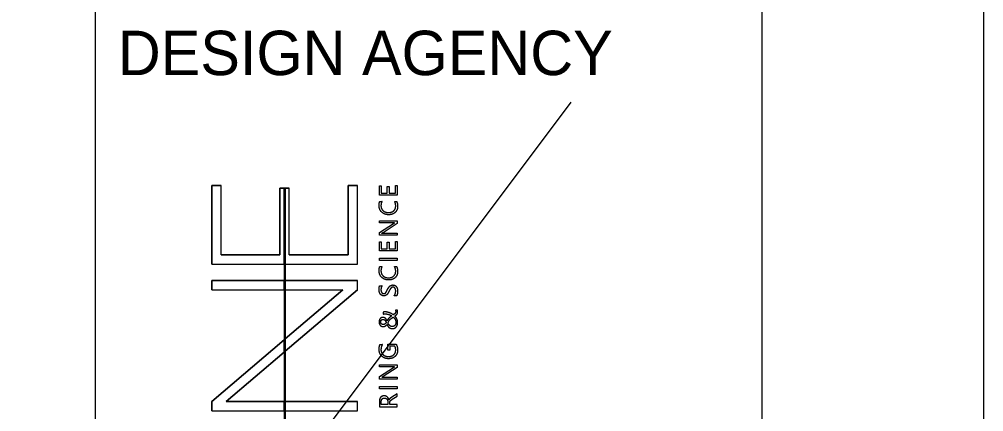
# Model space of a CAD drawing. Extents: x 0 to 34, y -1.8 to 22.
# Drawn here: x 31.828 to 34, y 3.592 to 4.476 of the extents above; entities that cross this region are included whole.
import ezdxf

# ---------------------------------------------------------------- set-up
doc = ezdxf.new("R2010")
doc.units = 0
for name, color, linetype in [('CS-ALGN-TEXT', 7, 'Continuous'), ('CS-ANNO', 7, 'Continuous'), ('CS-ANNO-MATC', 7, 'Continuous'), ('CS-PROF-TEXT', 7, 'Continuous')]:
    doc.layers.add(name, color=color, linetype=linetype)

msp = doc.modelspace()

# ---------------------------------------------------------------- linework, layer by layer
at = {"layer": 'CS-ALGN-TEXT'}
msp.add_lwpolyline([(0, 0), (34, 0), (34, 22), (0, 22)], close=True, dxfattribs=at)
at = {"layer": 'CS-ANNO'}
msp.add_line((32, 0.5), (32, 21.5), dxfattribs=at)
msp.add_lwpolyline([(1.5, 21.5), (33.5, 21.5), (33.5, 0.5), (1.5, 0.5)], close=True, dxfattribs=at)
at = {"layer": 'CS-ANNO-MATC'}
for p, q in [((32.2617, 4.1013), (32.2828, 4.1013)), ((32.2617, 3.9242), (32.2617, 4.1013)), ((32.2828, 3.9453), (32.2828, 4.1013)), ((32.4151, 3.9453), (32.4151, 4.0956)), ((32.4151, 4.0956), (32.4244, 4.0956)), ((32.4244, 4.0956), (32.4244, 3.4676)), ((32.4244, 4.0956), (32.4244, 3.9242)), ((32.4244, 4.0956), (32.4269, 4.0956)), ((32.4269, 4.0956), (32.4269, 3.4676)), ((32.4269, 4.0956), (32.4269, 3.9242)), ((32.4269, 4.0956), (32.4362, 4.0956)), ((32.4362, 3.9453), (32.4362, 4.0956)), ((32.5685, 4.1013), (32.5896, 4.1013)), ((32.5685, 3.9453), (32.5685, 4.1013)), ((32.5896, 3.9242), (32.5896, 4.1013)), ((32.64, 4.0658), (32.645, 4.0658)), ((32.6731, 4.0658), (32.6777, 4.0658)), ((32.6734, 4.0173), (32.6734, 4.0174)), ((32.6446, 3.994), (32.6446, 3.9938)), ((32.2828, 3.9453), (32.4151, 3.9453)), ((32.4362, 3.9453), (32.5685, 3.9453)), ((32.2617, 3.9242), (32.4244, 3.9242)), ((32.4269, 3.9242), (32.5896, 3.9242)), ((32.64, 3.919), (32.645, 3.919)), ((32.6731, 3.919), (32.6777, 3.919)), ((32.2617, 3.8665), (32.2617, 3.8876)), ((32.2617, 3.8876), (32.4244, 3.8876)), ((32.2617, 3.8665), (32.4244, 3.8665)), ((32.4244, 3.8876), (32.4244, 3.8665)), ((32.4269, 3.8876), (32.4269, 3.8665)), ((32.4269, 3.8876), (32.5896, 3.8876)), ((32.4269, 3.7561), (32.5568, 3.8665)), ((32.5896, 3.8665), (32.4269, 3.7283)), ((32.4269, 3.8665), (32.5568, 3.8665)), ((32.5896, 3.8665), (32.5896, 3.8876)), ((32.6397, 3.8758), (32.6451, 3.8758)), ((32.6778, 3.853), (32.6722, 3.853)), ((32.6478, 3.8165), (32.6478, 3.812)), ((32.6793, 3.821), (32.675, 3.821)), ((32.6801, 3.8167), (32.6801, 3.8167)), ((32.6473, 3.8001), (32.6473, 3.8001)), ((32.6761, 3.793), (32.6761, 3.793)), ((32.2617, 3.6155), (32.4244, 3.7539)), ((32.4244, 3.7539), (32.4244, 3.7261)), ((32.4269, 3.7561), (32.4269, 3.7283)), ((32.6404, 3.7435), (32.6457, 3.7435)), ((32.4244, 3.7261), (32.2943, 3.6155)), ((32.6734, 3.6931), (32.6734, 3.6932)), ((32.6446, 3.6698), (32.6446, 3.6696)), ((32.2617, 3.5944), (32.2617, 3.6155)), ((32.2943, 3.6155), (32.4244, 3.6155)), ((32.4244, 3.6155), (32.4244, 3.5944)), ((32.4269, 3.6155), (32.4269, 3.5944)), ((32.4269, 3.6155), (32.5896, 3.6155)), ((32.5896, 3.5944), (32.5896, 3.6155)), ((32.6607, 3.6189), (32.6606, 3.6189)), ((32.2617, 3.5944), (32.4244, 3.5944)), ((32.4269, 3.5944), (32.5896, 3.5944))]:
    msp.add_line(p, q, dxfattribs=at)
for points in [[(32.2617, 4.1013), (32.2617, 3.9242), (32.4244, 3.9242), (32.4244, 4.0956), (32.4151, 4.0956), (32.4151, 3.9453), (32.2828, 3.9453), (32.2828, 4.1013)], [(32.4362, 3.9453), (32.4362, 4.0956), (32.4269, 4.0956), (32.4269, 3.9242), (32.5896, 3.9242), (32.5896, 4.1013), (32.5685, 4.1013), (32.5685, 3.9453)], [(32.6794, 4.1013), (32.6794, 4.0799), (32.639, 4.0799), (32.639, 4.1004), (32.6433, 4.1004), (32.6433, 4.0846), (32.6567, 4.0846), (32.6567, 4.0992), (32.661, 4.0992), (32.661, 4.0846), (32.6751, 4.0846), (32.6751, 4.1013)], [(32.6794, 3.9757), (32.6794, 3.9542), (32.639, 3.9542), (32.639, 3.9747), (32.6433, 3.9747), (32.6433, 3.959), (32.6567, 3.959), (32.6567, 3.9736), (32.661, 3.9736), (32.661, 3.959), (32.6751, 3.959), (32.6751, 3.9757)], [(32.6794, 3.9377), (32.6794, 3.933), (32.639, 3.933), (32.639, 3.9377)], [(32.2617, 3.8876), (32.2617, 3.8665), (32.4244, 3.8665), (32.4244, 3.8876)], [(32.4269, 3.8876), (32.4269, 3.8665), (32.5568, 3.8665), (32.4269, 3.7561), (32.4269, 3.7283), (32.5896, 3.8665), (32.5896, 3.8876)], [(32.2617, 3.6155), (32.2617, 3.5944), (32.4244, 3.5944), (32.4244, 3.6155), (32.2943, 3.6155), (32.4244, 3.7261), (32.4244, 3.7539)], [(32.6794, 3.6486), (32.6794, 3.6439), (32.639, 3.6439), (32.639, 3.6486)], [(32.4269, 3.6155), (32.4269, 3.5944), (32.5896, 3.5944), (32.5896, 3.6155)]]:
    msp.add_lwpolyline(points, close=True, dxfattribs=at)
for points in [[(32.5359, 3.464), (32.4295, 3.4377), (32.4295, 3.4676), (32.4269, 3.4676), (32.4269, 4.0956), (32.4244, 4.0956), (32.4244, 3.4676), (32.4219, 3.4676), (32.4219, 3.4358), (32.3625, 3.4211)], [(32.6675, 4.0171), (32.639, 4.0171), (32.639, 4.0219), (32.6794, 4.0219), (32.6794, 4.0161), (32.6472, 3.9953)], [(32.6502, 3.994), (32.6794, 3.994), (32.6794, 3.9893), (32.639, 3.9893), (32.639, 3.9954), (32.6707, 4.0157)], [(32.6739, 3.7396), (32.6626, 3.7396), (32.6626, 3.7308), (32.6583, 3.7308), (32.6583, 3.7444), (32.6766, 3.7444)], [(32.6675, 3.6929), (32.639, 3.6929), (32.639, 3.6977), (32.6794, 3.6977), (32.6794, 3.6919), (32.6472, 3.6711)], [(32.6502, 3.6698), (32.6794, 3.6698), (32.6794, 3.6651), (32.639, 3.6651), (32.639, 3.6712), (32.6707, 3.6915)], [(32.6681, 3.6201), (32.6794, 3.6268), (32.6794, 3.6325), (32.6673, 3.6249)], [(32.639, 3.6156), (32.639, 3.6035), (32.6794, 3.6035), (32.6794, 3.6082), (32.6622, 3.6082), (32.6622, 3.6121)], [(32.6579, 3.6147), (32.6579, 3.6082), (32.6433, 3.6082), (32.6433, 3.6147)]]:
    msp.add_lwpolyline(points, dxfattribs=at)
for points in [[(32.6383, 4.0563), (32.6383, 4.062), (32.64, 4.0658)], [(32.645, 4.0658), (32.6426, 4.0615), (32.6426, 4.0562)], [(32.6758, 4.0553), (32.6758, 4.0614), (32.6731, 4.0658)], [(32.6777, 4.0658), (32.6801, 4.0613), (32.6801, 4.0547)], [(32.6443, 4.0415), (32.6383, 4.0473), (32.6383, 4.0563)], [(32.6426, 4.0562), (32.6426, 4.0493), (32.6472, 4.0449)], [(32.66, 4.0357), (32.6503, 4.0357), (32.6443, 4.0415)], [(32.6472, 4.0449), (32.6519, 4.0406), (32.6597, 4.0406)], [(32.6597, 4.0406), (32.6671, 4.0406), (32.6714, 4.0447)], [(32.6745, 4.0408), (32.669, 4.0357), (32.66, 4.0357)], [(32.6714, 4.0447), (32.6758, 4.0487), (32.6758, 4.0553)], [(32.6801, 4.0547), (32.6801, 4.046), (32.6745, 4.0408)], [(32.6734, 4.0174), (32.6717, 4.0171), (32.6675, 4.0171)], [(32.6707, 4.0157), (32.6727, 4.0169), (32.6734, 4.0173)], [(32.6472, 3.9953), (32.646, 3.9945), (32.6446, 3.994)], [(32.6446, 3.9938), (32.6459, 3.994), (32.6502, 3.994)], [(32.6383, 3.9094), (32.6383, 3.9152), (32.64, 3.919)], [(32.645, 3.919), (32.6426, 3.9146), (32.6426, 3.9094)], [(32.6758, 3.9084), (32.6758, 3.9145), (32.6731, 3.919)], [(32.6777, 3.919), (32.6801, 3.9145), (32.6801, 3.9078)], [(32.6443, 3.8946), (32.6383, 3.9005), (32.6383, 3.9094)], [(32.6426, 3.9094), (32.6426, 3.9024), (32.6472, 3.8981)], [(32.66, 3.8888), (32.6503, 3.8888), (32.6443, 3.8946)], [(32.6472, 3.8981), (32.6519, 3.8937), (32.6597, 3.8937)], [(32.6597, 3.8937), (32.6671, 3.8937), (32.6714, 3.8978)], [(32.6745, 3.894), (32.669, 3.8888), (32.66, 3.8888)], [(32.6714, 3.8978), (32.6758, 3.9018), (32.6758, 3.9084)], [(32.6801, 3.9078), (32.6801, 3.8992), (32.6745, 3.894)], [(32.6383, 3.8671), (32.6383, 3.8731), (32.6397, 3.8758)], [(32.6389, 3.862), (32.6383, 3.8645), (32.6383, 3.8671)], [(32.6451, 3.8758), (32.6426, 3.8723), (32.6426, 3.8667)], [(32.6426, 3.8667), (32.6426, 3.8651), (32.6429, 3.8636)], [(32.6552, 3.8631), (32.6561, 3.8647), (32.6571, 3.8668)], [(32.6571, 3.8668), (32.6582, 3.869), (32.6594, 3.8709)], [(32.6594, 3.8709), (32.6606, 3.8729), (32.662, 3.8744)], [(32.6626, 3.8669), (32.6616, 3.8651), (32.6606, 3.8631)], [(32.662, 3.8744), (32.6634, 3.8758), (32.6652, 3.8767)], [(32.6645, 3.8699), (32.6635, 3.8686), (32.6626, 3.8669)], [(32.6667, 3.8719), (32.6655, 3.8711), (32.6645, 3.8699)], [(32.6652, 3.8767), (32.6669, 3.8775), (32.6692, 3.8775)], [(32.6695, 3.8726), (32.6679, 3.8726), (32.6667, 3.8719)], [(32.6692, 3.8775), (32.6722, 3.8775), (32.6743, 3.8764)], [(32.6742, 3.8704), (32.6726, 3.8726), (32.6695, 3.8726)], [(32.6758, 3.8639), (32.6758, 3.8683), (32.6742, 3.8704)], [(32.6743, 3.8764), (32.6763, 3.8752), (32.6776, 3.8732)], [(32.6776, 3.8732), (32.6789, 3.8712), (32.6795, 3.8686)], [(32.6795, 3.8686), (32.6801, 3.866), (32.6801, 3.8632)], [(32.6409, 3.8575), (32.6396, 3.8595), (32.6389, 3.862)], [(32.6443, 3.8543), (32.6422, 3.8555), (32.6409, 3.8575)], [(32.6429, 3.8636), (32.6432, 3.862), (32.644, 3.8608)], [(32.644, 3.8608), (32.6447, 3.8596), (32.6459, 3.8588)], [(32.6491, 3.8531), (32.6463, 3.8531), (32.6443, 3.8543)], [(32.6459, 3.8588), (32.647, 3.8581), (32.6487, 3.8581)], [(32.6487, 3.8581), (32.6502, 3.8581), (32.6514, 3.8586)], [(32.653, 3.8539), (32.6514, 3.8531), (32.6491, 3.8531)], [(32.6514, 3.8586), (32.6525, 3.8592), (32.6534, 3.8603)], [(32.656, 3.856), (32.6547, 3.8546), (32.653, 3.8539)], [(32.6534, 3.8603), (32.6543, 3.8615), (32.6552, 3.8631)], [(32.6585, 3.8592), (32.6574, 3.8573), (32.656, 3.856)], [(32.6606, 3.8631), (32.6596, 3.861), (32.6585, 3.8592)], [(32.6722, 3.853), (32.673, 3.854), (32.6737, 3.8553)], [(32.6737, 3.8553), (32.6744, 3.8567), (32.6749, 3.8582)], [(32.6749, 3.8582), (32.6753, 3.8596), (32.6756, 3.8611)], [(32.6756, 3.8611), (32.6758, 3.8626), (32.6758, 3.8639)], [(32.6787, 3.8551), (32.6783, 3.8538), (32.6778, 3.853)], [(32.6795, 3.8579), (32.6792, 3.8564), (32.6787, 3.8551)], [(32.6799, 3.8608), (32.6798, 3.8594), (32.6795, 3.8579)], [(32.6801, 3.8632), (32.6801, 3.8622), (32.6799, 3.8608)], [(32.6406, 3.8016), (32.6395, 3.8003), (32.6389, 3.7985)], [(32.6433, 3.8037), (32.6418, 3.8029), (32.6406, 3.8016)], [(32.6469, 3.8044), (32.6449, 3.8044), (32.6433, 3.8037)], [(32.6525, 3.8025), (32.6503, 3.8044), (32.6469, 3.8044)], [(32.6496, 3.8168), (32.6487, 3.8167), (32.6478, 3.8165)], [(32.6478, 3.812), (32.6487, 3.8122), (32.6497, 3.8124)], [(32.6516, 3.8169), (32.6504, 3.8168), (32.6496, 3.8168)], [(32.6497, 3.8124), (32.6506, 3.8125), (32.6517, 3.8125)], [(32.6567, 3.8163), (32.6541, 3.8169), (32.6516, 3.8169)], [(32.6517, 3.8125), (32.6559, 3.8125), (32.6597, 3.8113)], [(32.6563, 3.7967), (32.6547, 3.8005), (32.6525, 3.8025)], [(32.6617, 3.8149), (32.6593, 3.8158), (32.6567, 3.8163)], [(32.6606, 3.8031), (32.6593, 3.8018), (32.6582, 3.8002)], [(32.6597, 3.8113), (32.6636, 3.8102), (32.6667, 3.8079)], [(32.6635, 3.8056), (32.662, 3.8045), (32.6606, 3.8031)], [(32.6664, 3.8128), (32.6642, 3.814), (32.6617, 3.8149)], [(32.6625, 3.7992), (32.6639, 3.8007), (32.6658, 3.8021)], [(32.6667, 3.8079), (32.6651, 3.8068), (32.6635, 3.8056)], [(32.6658, 3.8021), (32.6677, 3.8036), (32.6704, 3.8053)], [(32.6704, 3.8103), (32.6686, 3.8116), (32.6664, 3.8128)], [(32.6728, 3.8121), (32.6718, 3.8113), (32.6704, 3.8103)], [(32.6704, 3.8053), (32.6715, 3.8043), (32.6725, 3.803)], [(32.6725, 3.803), (32.6736, 3.8018), (32.6743, 3.8003)], [(32.6744, 3.8137), (32.6738, 3.8129), (32.6728, 3.8121)], [(32.6738, 3.8075), (32.6753, 3.8086), (32.6764, 3.8095)], [(32.6761, 3.8049), (32.675, 3.8064), (32.6738, 3.8075)], [(32.6754, 3.8154), (32.6751, 3.8146), (32.6744, 3.8137)], [(32.675, 3.821), (32.6753, 3.8201), (32.6755, 3.8192)], [(32.6758, 3.8175), (32.6758, 3.8163), (32.6754, 3.8154)], [(32.6755, 3.8192), (32.6758, 3.8183), (32.6758, 3.8175)], [(32.6781, 3.8016), (32.6773, 3.8034), (32.6761, 3.8049)], [(32.6764, 3.8095), (32.6776, 3.8105), (32.6784, 3.8116)], [(32.6795, 3.7977), (32.679, 3.7998), (32.6781, 3.8016)], [(32.6784, 3.8116), (32.6792, 3.8126), (32.6796, 3.8138)], [(32.6799, 3.8189), (32.6797, 3.82), (32.6793, 3.821)], [(32.6796, 3.8138), (32.6801, 3.8151), (32.6801, 3.8167)], [(32.6801, 3.8167), (32.6801, 3.8177), (32.6799, 3.8189)], [(32.6389, 3.7985), (32.6383, 3.7967), (32.6383, 3.7945)], [(32.6383, 3.7945), (32.6383, 3.7923), (32.6389, 3.7903)], [(32.6389, 3.7903), (32.6395, 3.7884), (32.6407, 3.787)], [(32.6407, 3.787), (32.6419, 3.7856), (32.6436, 3.7848)], [(32.642, 3.7945), (32.642, 3.7954), (32.6423, 3.7964)], [(32.6435, 3.7901), (32.642, 3.7917), (32.642, 3.7945)], [(32.6423, 3.7964), (32.6426, 3.7974), (32.6432, 3.7982)], [(32.6432, 3.7982), (32.6439, 3.799), (32.6449, 3.7995)], [(32.6475, 3.7884), (32.645, 3.7884), (32.6435, 3.7901)], [(32.6436, 3.7848), (32.6453, 3.784), (32.6475, 3.784)], [(32.6449, 3.7995), (32.6459, 3.8001), (32.6473, 3.8001)], [(32.6473, 3.8001), (32.6498, 3.8001), (32.6514, 3.7983)], [(32.6497, 3.7887), (32.6487, 3.7884), (32.6475, 3.7884)], [(32.6475, 3.784), (32.6491, 3.784), (32.6504, 3.7844)], [(32.6516, 3.7897), (32.6507, 3.7891), (32.6497, 3.7887)], [(32.6504, 3.7844), (32.6516, 3.7848), (32.6527, 3.7855)], [(32.6514, 3.7983), (32.6531, 3.7966), (32.6543, 3.793)], [(32.6532, 3.7912), (32.6525, 3.7904), (32.6516, 3.7897)], [(32.6527, 3.7855), (32.6538, 3.7861), (32.6546, 3.787)], [(32.6543, 3.793), (32.6538, 3.7921), (32.6532, 3.7912)], [(32.6546, 3.787), (32.6554, 3.7878), (32.656, 3.7887)], [(32.656, 3.7887), (32.658, 3.7842), (32.661, 3.7817)], [(32.6582, 3.8002), (32.6571, 3.7986), (32.6563, 3.7967)], [(32.6583, 3.7922), (32.6592, 3.7944), (32.6602, 3.796)], [(32.6599, 3.7889), (32.659, 3.7904), (32.6583, 3.7922)], [(32.6619, 3.7863), (32.6607, 3.7874), (32.6599, 3.7889)], [(32.6602, 3.796), (32.6611, 3.7977), (32.6625, 3.7992)], [(32.661, 3.7817), (32.6641, 3.7793), (32.6684, 3.7793)], [(32.6646, 3.7846), (32.6631, 3.7852), (32.6619, 3.7863)], [(32.6683, 3.784), (32.6662, 3.784), (32.6646, 3.7846)], [(32.6717, 3.7847), (32.6702, 3.784), (32.6683, 3.784)], [(32.6684, 3.7793), (32.6712, 3.7793), (32.6734, 3.7803)], [(32.6741, 3.7866), (32.6731, 3.7854), (32.6717, 3.7847)], [(32.6734, 3.7803), (32.6756, 3.7813), (32.6771, 3.7831)], [(32.6756, 3.7895), (32.6751, 3.7879), (32.6741, 3.7866)], [(32.6743, 3.8003), (32.6751, 3.7988), (32.6756, 3.797)], [(32.6756, 3.797), (32.6761, 3.7952), (32.6761, 3.793)], [(32.6761, 3.793), (32.6761, 3.7911), (32.6756, 3.7895)], [(32.6771, 3.7831), (32.6785, 3.7849), (32.6793, 3.7874)], [(32.6793, 3.7874), (32.6801, 3.79), (32.6801, 3.793)], [(32.6801, 3.793), (32.6801, 3.7955), (32.6795, 3.7977)], [(32.6383, 3.7325), (32.6383, 3.7391), (32.6404, 3.7435)], [(32.6457, 3.7435), (32.6426, 3.7386), (32.6426, 3.7319)], [(32.6758, 3.7314), (32.6758, 3.7361), (32.6739, 3.7396)], [(32.6766, 3.7444), (32.6801, 3.7383), (32.6801, 3.7308)], [(32.6443, 3.7174), (32.6383, 3.7233), (32.6383, 3.7325)], [(32.6426, 3.7319), (32.6426, 3.7251), (32.6473, 3.7208)], [(32.6597, 3.7115), (32.6503, 3.7115), (32.6443, 3.7174)], [(32.6473, 3.7208), (32.6519, 3.7164), (32.6594, 3.7164)], [(32.6594, 3.7164), (32.6671, 3.7164), (32.6714, 3.7205)], [(32.6745, 3.7168), (32.6689, 3.7115), (32.6597, 3.7115)], [(32.6714, 3.7205), (32.6758, 3.7245), (32.6758, 3.7314)], [(32.6801, 3.7308), (32.6801, 3.7222), (32.6745, 3.7168)], [(32.6734, 3.6932), (32.6717, 3.6929), (32.6675, 3.6929)], [(32.6707, 3.6915), (32.6727, 3.6928), (32.6734, 3.6931)], [(32.6472, 3.6711), (32.646, 3.6703), (32.6446, 3.6698)], [(32.6446, 3.6696), (32.6459, 3.6698), (32.6502, 3.6698)], [(32.6497, 3.6279), (32.647, 3.6279), (32.645, 3.6269)], [(32.6536, 3.6272), (32.6519, 3.6279), (32.6497, 3.6279)], [(32.6568, 3.6254), (32.6554, 3.6266), (32.6536, 3.6272)], [(32.6396, 3.6205), (32.639, 3.6182), (32.639, 3.6156)], [(32.6417, 3.6244), (32.6403, 3.6227), (32.6396, 3.6205)], [(32.645, 3.6269), (32.643, 3.626), (32.6417, 3.6244)], [(32.6433, 3.6147), (32.6433, 3.6187), (32.6451, 3.6208)], [(32.6451, 3.6208), (32.6469, 3.6229), (32.6501, 3.6229)], [(32.6501, 3.6229), (32.6519, 3.6229), (32.6534, 3.6223)], [(32.6534, 3.6223), (32.6549, 3.6217), (32.6559, 3.6206)], [(32.6559, 3.6206), (32.6569, 3.6195), (32.6574, 3.618)], [(32.6591, 3.6226), (32.6581, 3.6243), (32.6568, 3.6254)], [(32.6574, 3.618), (32.6579, 3.6164), (32.6579, 3.6147)], [(32.6606, 3.6189), (32.6601, 3.621), (32.6591, 3.6226)], [(32.6618, 3.6207), (32.6612, 3.6199), (32.6607, 3.6189)], [(32.6631, 3.6221), (32.6623, 3.6214), (32.6618, 3.6207)], [(32.6622, 3.6121), (32.6622, 3.6135), (32.6625, 3.6145)], [(32.6625, 3.6145), (32.6629, 3.6156), (32.6636, 3.6165)], [(32.6649, 3.6234), (32.6639, 3.6228), (32.6631, 3.6221)], [(32.6636, 3.6165), (32.6643, 3.6174), (32.6654, 3.6183)], [(32.6673, 3.6249), (32.6659, 3.6241), (32.6649, 3.6234)], [(32.6654, 3.6183), (32.6665, 3.6192), (32.6681, 3.6201)]]:
    msp.add_open_spline(points, degree=2, dxfattribs=at)
at = {"layer": 'CS-PROF-TEXT'}
msp.add_line((31.8706, 2.6892), (33.0706, 4.2892), dxfattribs=at)

# ---------------------------------------------------------------- texts
at = {"layer": 'CS-ANNO-MATC'}
msp.add_text('DESIGN AGENCY', height=0.1, dxfattribs=at).set_placement((32.05, 4.35))

doc.saveas('drawing.dxf')
